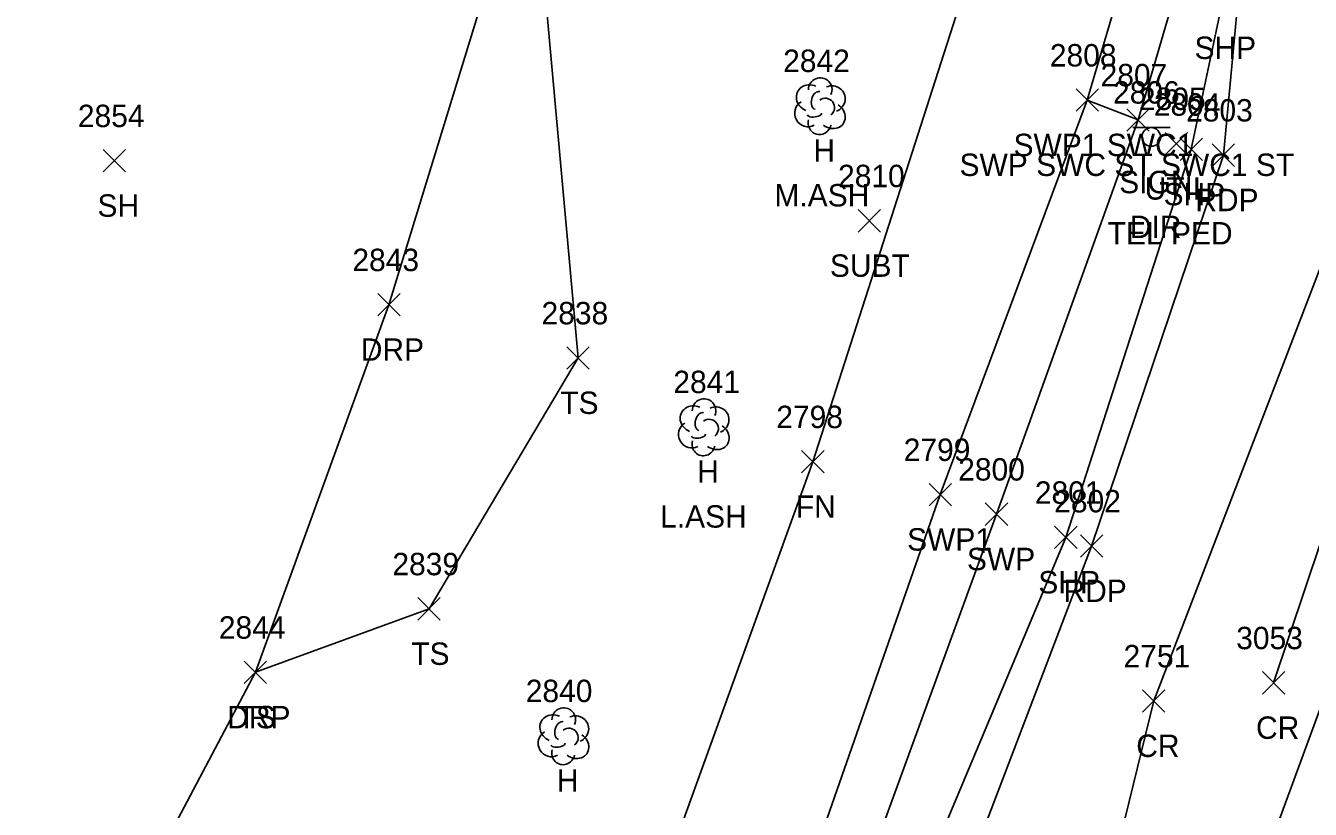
# Model space of a CAD drawing. Extents: x 1477930 to 1480780, y 774090 to 784647.
# Drawn here: x 1479402.4 to 1479517, y 775042.4 to 775112.3 of the extents above; entities that cross this region are included whole.
import ezdxf

# ---------------------------------------------------------------- set-up
doc = ezdxf.new("R2010")
doc.units = 0
for name, color, linetype in [('L_A', 7, 'Continuous'), ('L_C', 7, 'Continuous'), ('L_I', 7, 'Continuous'), ('L_TIC', 7, 'Continuous'), ('LELB', 7, 'Continuous'), ('LFNC', 7, 'Continuous'), ('LTD', 7, 'Continuous'), ('P_A', 7, 'Continuous'), ('P_I', 7, 'Continuous'), ('P_TIC', 7, 'Continuous'), ('PET', 7, 'Continuous'), ('PRC', 7, 'Continuous'), ('PSP', 7, 'Continuous'), ('R_A', 7, 'Continuous'), ('R_I', 7, 'Continuous'), ('R_TIC', 7, 'Continuous'), ('RDP', 7, 'Continuous'), ('RSW', 7, 'Continuous'), ('S_A', 7, 'Continuous'), ('S_C', 7, 'Continuous'), ('S_I', 7, 'Continuous'), ('SSGN', 7, 'Continuous'), ('U_A', 7, 'Continuous'), ('U_C', 7, 'Continuous'), ('U_I', 7, 'Continuous'), ('U_TIC', 7, 'Continuous'), ('UDEFAULT', 7, 'Continuous')]:
    doc.layers.add(name, color=color, linetype=linetype)

msp = doc.modelspace()

# ---------------------------------------------------------------- linework, layer by layer
at = {"layer": 'L_TIC'}
for points in [[(1479409.31, 775099.29), (1479411.31, 775101.29)], [(1479411.31, 775099.29), (1479409.31, 775101.29)], [(1479450.69, 775081.69), (1479452.69, 775083.69)], [(1479452.69, 775081.69), (1479450.69, 775083.69)], [(1479471.64, 775072.43), (1479473.64, 775074.43)], [(1479473.64, 775072.43), (1479471.64, 775074.43)], [(1479437.39, 775059.3), (1479439.39, 775061.3)], [(1479439.39, 775059.3), (1479437.39, 775061.3)], [(1479421.89, 775053.64), (1479423.89, 775055.64)], [(1479423.89, 775053.64), (1479421.89, 775055.64)]]:
    msp.add_lwpolyline(points, dxfattribs=at)
at = {"layer": 'LELB'}
msp.add_lwpolyline([(1479488.58, 775153.52), (1479475.94, 775152.23), (1479464.58, 775146.24), (1479448.41, 775119.27), (1479451.69, 775082.69), (1479438.39, 775060.3), (1479422.89, 775054.64)], dxfattribs=at)
at = {"layer": 'LFNC'}
msp.add_lwpolyline([(1479373.09, 774875.08), (1479392.41, 774904.48), (1479409.31, 774932.95), (1479448.69, 775010.76), (1479458.93, 775035.46), (1479472.64, 775073.43), (1479490.33, 775128.57)], dxfattribs=at)
at = {"layer": 'LTD'}
for p, q in [((1479473.25, 775105.21), (1479473.25, 775105.21)), ((1479473.25, 775105.21), (1479473.25, 775105.21)), ((1479462.89, 775076.55), (1479462.89, 775076.55)), ((1479462.89, 775076.55), (1479462.89, 775076.55)), ((1479450.37, 775048.98), (1479450.37, 775048.98)), ((1479450.37, 775048.98), (1479450.37, 775048.98))]:
    msp.add_line(p, q, dxfattribs=at)
for centre in [(1479473.3, 775106.64), (1479462.93, 775077.99), (1479450.41, 775050.42)]:
    msp.add_arc(centre, 1.05, 335.5272, 180.9563, dxfattribs=at)
for centre, major_axis, ratio, start_param, end_param in [((1479472.46, 775105.87), (1.21, -0.51), 0.895232, 1.570796, 4.712389), ((1479474.3, 775105.79), (-1.14, -0.48), 0.949671, 1.570796, 4.712389), ((1479472.17, 775104.5), (0.58, -1.04), 0.959034, 3.141593, 6.283185), ((1479473.05, 775105.67), (-0.208, -0.792), 0.645439, 3.141593, 6.283185), ((1479473.75, 775105.04), (-0.5, 0.667), 0.989748, 3.141593, 6.283185), ((1479472.8, 775104.46), (-0.625, -0.083), 0.423636, 0, 3.141593), ((1479474.25, 775104.37), (-1.09, 0.79), 0.841452, 1.570796, 4.712389), ((1479473.25, 775103.71), (0.26, 1.06), 0.942809, 1.570796, 4.712389), ((1479462.09, 775077.22), (1.21, -0.51), 0.895232, 1.570796, 4.712389), ((1479463.93, 775077.14), (-1.14, -0.48), 0.949671, 1.570796, 4.712389), ((1479461.8, 775075.84), (0.58, -1.04), 0.959034, 3.141593, 6.283185), ((1479462.68, 775077.01), (-0.208, -0.792), 0.645439, 3.141593, 6.283185), ((1479463.39, 775076.39), (-0.5, 0.667), 0.989748, 3.141593, 6.283185), ((1479462.43, 775075.8), (-0.625, -0.083), 0.423636, 0, 3.141593), ((1479463.89, 775075.72), (-1.09, 0.79), 0.841452, 1.570796, 4.712389), ((1479462.89, 775075.05), (0.26, 1.06), 0.942809, 1.570796, 4.712389), ((1479449.57, 775049.65), (1.21, -0.51), 0.895232, 1.570796, 4.712389), ((1479451.41, 775049.57), (-1.14, -0.48), 0.949671, 1.570796, 4.712389), ((1479450.16, 775049.44), (-0.208, -0.792), 0.645439, 3.141593, 6.283185), ((1479450.87, 775048.82), (-0.5, 0.667), 0.989748, 3.141593, 6.283185), ((1479449.28, 775048.28), (0.58, -1.04), 0.959034, 3.141593, 6.283185), ((1479449.91, 775048.23), (-0.625, -0.083), 0.423636, 0, 3.141593), ((1479451.37, 775048.15), (-1.09, 0.79), 0.841452, 1.570796, 4.712389), ((1479450.37, 775047.48), (0.26, 1.06), 0.942809, 1.570796, 4.712389)]:
    msp.add_ellipse(centre, major_axis=major_axis, ratio=ratio, start_param=start_param, end_param=end_param, dxfattribs=at)
at = {"layer": 'P_TIC'}
for points in [[(1479505.41, 775100.31), (1479507.41, 775102.31)], [(1479507.41, 775100.31), (1479505.41, 775102.31)], [(1479508.28, 775099.79), (1479510.28, 775101.79)], [(1479510.28, 775099.79), (1479508.28, 775101.79)], [(1479494.22, 775065.68), (1479496.22, 775067.68)], [(1479496.22, 775065.68), (1479494.22, 775067.68)], [(1479496.52, 775064.91), (1479498.52, 775066.91)], [(1479498.52, 775064.91), (1479496.52, 775066.91)], [(1479512.76, 775052.7), (1479514.76, 775054.7)], [(1479514.76, 775052.7), (1479512.76, 775054.7)], [(1479502.06, 775051.08), (1479504.06, 775053.08)], [(1479504.06, 775051.08), (1479502.06, 775053.08)]]:
    msp.add_lwpolyline(points, dxfattribs=at)
at = {"layer": 'PET'}
msp.add_lwpolyline([(1479168.73, 774620.31), (1479212.4, 774655.38), (1479259.7, 774697.56), (1479293.15, 774732.73), (1479318.8, 774762.89), (1479333.57, 774781.21), (1479355.81, 774805.14), (1479380.51, 774839), (1479394.88, 774859.45), (1479419.72, 774898.43), (1479440.51, 774934.48), (1479462.36, 774978.06), (1479482.36, 775026.15), (1479497.52, 775065.91), (1479509.28, 775100.79), (1479510.93, 775118.31)], dxfattribs=at)
at = {"layer": 'PRC'}
for points in [[(1479587.72, 775307.65), (1479575.01, 775262.49), (1479563.12, 775220.83), (1479548.57, 775168.37), (1479533.5, 775112.54), (1479513.76, 775053.7)], [(1479430.01, 774890.62), (1479468.91, 774957.83), (1479493.21, 775011.92), (1479503.06, 775052.08), (1479530.4, 775123.25), (1479541.54, 775166.06), (1479555.58, 775209.55), (1479571.78, 775263.31), (1479582.9, 775300.17)], [(1479438.76, 774885), (1479466.69, 774929.85), (1479479.06, 774955.89), (1479501.08, 775005.62), (1479520.94, 775059.64), (1479540.23, 775118.92), (1479552.22, 775163.96), (1479564.07, 775206.06), (1479578.9, 775260.88), (1479588.27, 775297.78)]]:
    msp.add_lwpolyline(points, dxfattribs=at)
at = {"layer": 'PSP'}
msp.add_lwpolyline([(1479333.57, 774781.21), (1479353.18, 774806.91), (1479376.82, 774840.34), (1479390.8, 774862.22), (1479415.7, 774900.26), (1479436.53, 774936.29), (1479458.59, 774979.44), (1479478.64, 775027.16), (1479495.22, 775066.68), (1479506.41, 775101.31), (1479509.16, 775114.37), (1479508.43, 775127.01)], dxfattribs=at)
at = {"layer": 'R_TIC'}
for points in [[(1479496.13, 775104.7), (1479498.13, 775106.7)], [(1479498.13, 775104.7), (1479496.13, 775106.7)], [(1479496.13, 775104.7), (1479498.13, 775106.7)], [(1479498.13, 775104.7), (1479496.13, 775106.7)], [(1479500.66, 775102.93), (1479502.66, 775104.93)], [(1479502.66, 775102.93), (1479500.66, 775104.93)], [(1479500.66, 775102.93), (1479502.66, 775104.93)], [(1479502.66, 775102.93), (1479500.66, 775104.93)], [(1479500.66, 775102.93), (1479502.66, 775104.93)], [(1479502.66, 775102.93), (1479500.66, 775104.93)], [(1479433.81, 775086.44), (1479435.81, 775088.44)], [(1479435.81, 775086.44), (1479433.81, 775088.44)], [(1479483.01, 775069.5), (1479485.01, 775071.5)], [(1479485.01, 775069.5), (1479483.01, 775071.5)], [(1479488.03, 775067.75), (1479490.03, 775069.75)], [(1479490.03, 775067.75), (1479488.03, 775069.75)], [(1479421.89, 775053.64), (1479423.89, 775055.64)], [(1479423.89, 775053.64), (1479421.89, 775055.64)], [(1479421.89, 775053.64), (1479423.89, 775055.64)], [(1479423.89, 775053.64), (1479421.89, 775055.64)]]:
    msp.add_lwpolyline(points, dxfattribs=at)
at = {"layer": 'RDP'}
for points in [[(1479505.94, 775135.56), (1479488.58, 775153.52), (1479475.65, 775155.28), (1479462.78, 775150.22), (1479453.24, 775141.44), (1479444.68, 775119.64), (1479434.81, 775087.44), (1479422.89, 775054.64)], [(1479341.82, 774898.99), (1479353.71, 774920.58), (1479370.62, 774953.72), (1479387.55, 774986.35), (1479411.83, 775033.72), (1479422.89, 775054.64)]]:
    msp.add_lwpolyline(points, dxfattribs=at)
at = {"layer": 'RSW'}
for points in [[(1479501.66, 775103.93), (1479497.13, 775105.7), (1479505.94, 775135.56)], [(1479501.66, 775103.93), (1479508.43, 775127.01), (1479507.78, 775131.3)], [(1479274.17, 774731.39), (1479308.42, 774770.17), (1479343.53, 774813.46), (1479368.77, 774847.04), (1479380.89, 774863.8), (1479383.37, 774867.44), (1479386.24, 774871.51), (1479407.11, 774905.13), (1479428.53, 774941.71), (1479450.08, 774982.66), (1479469.96, 775030.3), (1479484.01, 775070.5), (1479497.13, 775105.7)], [(1479277.58, 774728.25), (1479312.53, 774767.11), (1479348.01, 774809.99), (1479373.39, 774844.03), (1479387.54, 774864.22), (1479390.19, 774868.27), (1479411.38, 774902.61), (1479432.83, 774938.99), (1479454.5, 774980.05), (1479474.41, 775028.7), (1479489.03, 775068.75), (1479501.66, 775103.93)]]:
    msp.add_lwpolyline(points, dxfattribs=at)
at = {"layer": 'SSGN'}
for p, q in [((1479501.2, 775103.25), (1479504.53, 775103.25)), ((1479502.84, 775102.41), (1479502.84, 775102.41))]:
    msp.add_line(p, q, dxfattribs=at)
msp.add_circle((1479502.84, 775102.41), 0.833, dxfattribs=at)
at = {"layer": 'U_TIC'}
for points in [[(1479476.67, 775093.93), (1479478.67, 775095.93)], [(1479478.67, 775093.93), (1479476.67, 775095.93)]]:
    msp.add_lwpolyline(points, dxfattribs=at)
at = {"layer": 'UDEFAULT'}
for points in [[(1479504.08, 775100.82), (1479506.08, 775102.82)], [(1479506.08, 775100.82), (1479504.08, 775102.82)]]:
    msp.add_lwpolyline(points, dxfattribs=at)

# ---------------------------------------------------------------- texts
at = {"layer": 'L_A'}
for s, p in [('H', (1479472.69, 775100.21)), ('SH', (1479408.8, 775095.29)), ('TS', (1479450.1, 775077.69)), ('H', (1479462.32, 775071.55)), ('FN', (1479471.12, 775068.43)), ('TS', (1479436.8, 775055.3)), ('TS', (1479421.3, 775049.64)), ('H', (1479449.8, 775043.98))]:
    msp.add_text(s, height=2, dxfattribs=at).set_placement(p)
at = {"layer": 'L_C'}
for s, p in [('M.ASH', (1479469.21, 775096.21)), ('L.ASH', (1479459.01, 775067.55))]:
    msp.add_text(s, height=2, dxfattribs=at).set_placement(p)
at = {"layer": 'L_I'}
for s, p in [('2842', (1479469.99, 775108.21)), ('2854', (1479407.05, 775103.29)), ('2838', (1479448.43, 775085.69)), ('2841', (1479460.19, 775079.55)), ('2798', (1479469.38, 775076.43)), ('2839', (1479435.12, 775063.3)), ('2844', (1479419.63, 775057.64)), ('2840', (1479447.02, 775051.98))]:
    msp.add_text(s, height=2, dxfattribs=at).set_placement(p)
at = {"layer": 'P_A'}
for s, p in [('SHP', (1479506.7, 775109.37)), ('SHP', (1479503.94, 775096.31)), ('RDP', (1479506.77, 775095.79)), ('SHP', (1479492.76, 775061.68)), ('RDP', (1479495.01, 775060.91)), ('CR', (1479512.19, 775048.7)), ('CR', (1479501.5, 775047.08))]:
    msp.add_text(s, height=2, dxfattribs=at).set_placement(p)
at = {"layer": 'P_I'}
for s, p in [('2804', (1479503.07, 775104.31)), ('2803', (1479505.95, 775103.79)), ('2801', (1479492.45, 775069.68)), ('2802', (1479494.18, 775068.91)), ('3053', (1479510.42, 775056.7)), ('2751', (1479500.37, 775055.08))]:
    msp.add_text(s, height=2, dxfattribs=at).set_placement(p)
at = {"layer": 'R_A'}
for s, p in [('SWP1 SWC1', (1479490.55, 775100.7)), ('SWP1 SWC1', (1479490.55, 775100.7)), ('SWP SWC ST SWC1 ST', (1479485.73, 775098.93)), ('SWP SWC ST SWC1 ST', (1479485.73, 775098.93)), ('SWP SWC ST SWC1 ST', (1479485.73, 775098.93)), ('DRP', (1479432.3, 775082.44)), ('SWP1', (1479481.05, 775065.5)), ('SWP', (1479486.39, 775063.75)), ('DRP', (1479420.38, 775049.64)), ('DRP', (1479420.38, 775049.64))]:
    msp.add_text(s, height=2, dxfattribs=at).set_placement(p)
at = {"layer": 'R_I'}
for s, p in [('2808', (1479493.79, 775108.7)), ('2808', (1479493.79, 775108.7)), ('2807', (1479498.32, 775106.93)), ('2807', (1479498.32, 775106.93)), ('2807', (1479498.32, 775106.93)), ('2843', (1479431.55, 775090.44)), ('2799', (1479480.75, 775073.5)), ('2800', (1479485.61, 775071.75)), ('2844', (1479419.63, 775057.64)), ('2844', (1479419.63, 775057.64))]:
    msp.add_text(s, height=2, dxfattribs=at).set_placement(p)
at = {"layer": 'S_A'}
msp.add_text('SIGN', height=2, dxfattribs=at).set_placement((1479499.98, 775097.39))
at = {"layer": 'S_C'}
msp.add_text('DIR', height=2, dxfattribs=at).set_placement((1479500.93, 775093.39))
at = {"layer": 'S_I'}
msp.add_text('2806', height=2, dxfattribs=at).set_placement((1479499.43, 775105.39))
at = {"layer": 'U_A'}
for s, p in [('UTIL', (1479502.25, 775096.82)), ('SUBT', (1479474.16, 775089.93))]:
    msp.add_text(s, height=2, dxfattribs=at).set_placement(p)
at = {"layer": 'U_C'}
msp.add_text('TEL PED', height=2, dxfattribs=at).set_placement((1479498.95, 775092.82))
at = {"layer": 'U_I'}
for s, p in [('2805', (1479501.74, 775104.82)), ('2810', (1479474.89, 775097.93))]:
    msp.add_text(s, height=2, dxfattribs=at).set_placement(p)

doc.saveas('drawing.dxf')
